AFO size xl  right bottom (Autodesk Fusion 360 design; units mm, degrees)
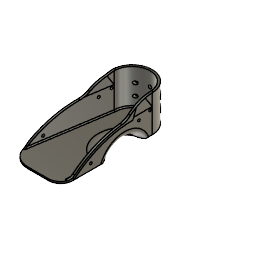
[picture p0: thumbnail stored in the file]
part number: 2025-10-02-12-56-12-317
parameter "d73" = 49
parameter "d131" = 16
sketch "Sketch1" plane through (0, 0, 0) normal (0, 0, 1) x axis (1, 0, 0)
  line L1 (28, -127.4) -> (-48, -127.4)
  line L2 (28, 0) -> (28, -127.4)
  line L3 (25, 0) -> (25, -127.4)
  line L4 (28, 0) -> (25, 0)
  line L5 (-18.603, -127.4) -> (-18.603, -115.6)
  line L6 (10.5, -127.4) -> (10.5, -109.9)
  line L7 (10.5, -127.4) -> (-18.603, -127.4)
  line L8 (36.7314, -101.9) -> (-43.9969, -101.9)
  line L9 (0, 0) -> (-28.984, 0)
  line L10 (-45, -127.4) -> (-25, 0)
  line L11 (-40.9969, -101.9) -> (-44.0794, -101.4161)
  line L12 (-48, -127.4) -> (-28, 0)
  line L13 (-43.6846, -101.9) -> (-43.6828, -102.2021)
  circle C1 centre (0, 0) radius 28
  circle C2 centre (0, 0) radius 25
  circle C3 centre (10.5, -109.9) radius 17.5
  circle C4 centre (-18.1846, -101.9) radius 22.5
  circle C5 centre (10.5, -109.9) radius 14.5
  circle C6 centre (-18.1846, -101.9) radius 25.5
  point P1 (0, 0)
  point P2 (0, 0)
  point P5 (28, 0)
  point P6 (0, 0)
  point P7 (25, 0)
  point P8 (25, -127.4)
  point P13 (-18.603, -127.4)
  point P11 (10.5, -109.9)
  point P14 (10.5, -109.9)
  point P15 (10.5, -127.4)
  point P20 (-25, 0)
  point P21 (-45, -127.4)
  point P22 (-40.9969, -101.9)
  point P10 (-18.1846, -101.9)
  point P25 (-28, 0)
  point P16 (-43.9969, -101.9)
  point P26 (-43.6828, -102.2021)
  point P27 (-43.6846, -101.9)
  point P19 (0, 0)
  coincident P1 P2
  coincident C1 P5
  tangent C1 L2
  perpendicular L1 L2
  coincident P1 P6
  vertical L3
  coincident C2 P7
  perpendicular L2 L4
  coincident L1 P8
  tangent L2 C3
  tangent L1 C3
  concentric C3 C5
  tangent L3 C5
  coincident L1 P13
  perpendicular L1 L5
  coincident P11 P14
  coincident L1 P15
  coincident C3 P15
  perpendicular L1 L6
  perpendicular L5 L8
  horizontal L9
  coincident C2 P20
  coincident L9 P20
  coincident L1 P21
  coincident L10 P22
  coincident L8 P22
  parallel L2 L3
  coincident P10 L8
  concentric C4 C6
  coincident L9 P25
  coincident C1 P25
  parallel L10 L12
  coincident P16 L12
  coincident C6 P26
  coincident L8 P27
  coincident C6 P27
  coincident P1 P19
  tangent L1 C6
  tangent C6 L12
  perpendicular L11 L12
  dimension "d2" diameter C1 = 56 (= "d57 + ( 3 * 2 ) * 1 mm")
  dimension "d4" distance P2 L1 = 127.4 (= "152.4 mm - 25 mm")
  dimension "d57" diameter C2 = 50
  dimension "d74" diameter C3 = 35
  dimension "d252" diameter C4 = 45 (= "d73 - 4 mm")
  dimension "d322" distance P8 P21 = 70
  dimension "d323" diameter C6 = 51 (= "d252 + 6 mm")
extrude "Extrude1" new body sketch "Sketch1" profile of C1 L2 L3 L4 C3 L8 L9 L10 L11 C6 L12 along normal blind 35
extrude "Extrude2" add sketch "Sketch1" profile of C1 L1 L2 C2 L3 C3 C4 C5 L5 L6 L7 L8 L10 L11 C6 L13 along normal blind 3
extrude "Extrude15" new body sketch "Sketch1" profile of C1 C2 L4 L9 along normal blind 178
combine "Combine2"
work_plane "WorkPlane1" RotateAngle -90
fillet "Fillet69" radius 1 1
sketch "Sketch23" plane through (28, 0, 0) normal (1, 0, 0) x axis (0, 1, 0)
  line L1 (-28, 78) -> (0, 35)
  line L2 (-28, 178) -> (-28, 78)
  line L3 (0, 178) -> (-28, 178)
  line L4 (0, 35) -> (0, 178)
  circle C1 centre (-3, 143) radius 1.75
  point P5 (0, 178)
  point P6 (0, 178)
  point P2 (0, 35)
  point P8 (0, 35)
  point P4 (-28, 178)
  point P3 (-28, 78)
  point P7 (-3, 143)
  horizontal L3
  perpendicular L3 L4
  coincident P5 P6
  coincident P2 P8
  parallel L2 L4
  dimension "d253" distance P4 P5 = 28
  dimension "d254" distance P3 P4 = 100
  dimension "d255" diameter C1 = 3.5
  dimension "d256" distance L3 P7 = 35
  dimension "d257" distance L2 P7 = 25
extrude "Extrude18" add sketch "Sketch23" against normal blind 3
mirror "Mirror1" mirrorStitchTolerance 0.1
sketch "Sketch24" plane through (0, 16.0046, 10.4216) normal (0, -0.838, -0.5457) x axis (1, 0, 0)
  line L1 (-25, 80.6427) -> (-25, 29.3299)
  line L2 (-28, 80.6427) -> (-25, 80.6427)
  line L3 (-28, 29.3299) -> (-28, 80.6427)
  line L4 (-25, 62.182) -> (-28, 62.182)
  line L5 (-28, 30.2476) -> (-25, 30.2476)
  line L6 (-28, 30.2476) -> (-28, 62.182)
  line L7 (-25, 62.182) -> (-25, 30.2476)
  line L8 (-25, 29.3299) -> (-28, 29.3299)
  point P6 (-28, 62.182)
  point P7 (-25, 62.182)
  point P8 (-25, 30.2476)
  point P9 (-28, 30.2476)
  coincident L3 P6
  coincident L1 P7
  perpendicular L1 L4
  coincident L1 P8
  coincident L3 P9
  perpendicular L3 L5
sketch "Sketch25" plane through (0, 0, 35) normal (0, 0, 1) x axis (-1, 0, 0)
  line L1 (24.843, -1) -> (27.843, -1)
  line L2 (29.5678, 29.0967) -> (24.843, -1)
  line L3 (32.4956, 28.637) -> (29.5678, 29.0967)
  line L4 (32.4956, 28.637) -> (27.843, -1)
  line L5 (0, 0) -> (28.984, 0)
  line L6 (43.3761, 97.9455) -> (28, 0)
  line L7 (25, 0) -> (40.9969, 101.9)
  line L8 (28, 0) -> (25, 0)
  line L9 (40.9969, 101.9) -> (43.6811, 101.4786)
  arc A1 centre (18.1846, 101.9) radius 25.5 clockwise from (43.6811, 101.4786) to (43.3761, 97.9455)
  point P5 (32.4956, 28.637)
  point P4 (29.5678, 29.0967)
  point P15 (28, 0)
  point P8 (25, 0)
  point P2 (27.843, -1)
  horizontal L1
  coincident P5 L6
  coincident P4 L7
  coincident L4 P15
  coincident L2 P8
  perpendicular L3 L4
  dimension "d280" distance P2 P5 = 30
  dimension "d281" distance L1 L5 = 1
loft "Loft1" sketch "Sketch24" + "Sketch25"
sketch "Sketch26" plane through (0, 0, 35) normal (0, 0, 1) x axis (-1, 0, 0)
  line L1 (-28, 0) -> (-28, 101.9)
  line L2 (-25, 0) -> (-28, 0)
  line L3 (-28, -1) -> (-25, -1)
  line L4 (-28, -1) -> (-28, 29)
  line L5 (-25, 29) -> (-28, 29)
  line L6 (-25, -1) -> (-25, 29)
  line L7 (-28, 101.9) -> (-25, 101.9)
  line L8 (-25, 101.9) -> (-25, 0)
  point P5 (-28, -1)
  point P6 (-28, 29)
  point P7 (-25, 29)
  coincident L1 P5
  perpendicular L1 L3
  coincident L1 P6
  coincident P7 L8
  dimension "d278" distance P5 P6 = 30
  dimension "d279" distance L2 L3 = 1
sketch "Sketch27" plane through (0, 16.0046, 10.4216) normal (0, -0.838, -0.5457) x axis (1, 0, 0)
  line L1 (28, 80.6427) -> (28, 29.3299)
  line L2 (25, 80.6427) -> (28, 80.6427)
  line L3 (25, 29.3299) -> (25, 80.6427)
  line L4 (28, 29.3299) -> (25, 29.3299)
  line L5 (28, 63.1164) -> (25, 63.1164)
  line L6 (28, 32.1164) -> (28, 63.1164)
  line L7 (28, 32.1164) -> (25, 32.1164)
  line L8 (25, 63.1164) -> (25, 32.1164)
  point P6 (25, 63.1164)
  point P7 (28, 63.1164)
  point P8 (28, 32.1164)
  point P9 (25, 32.1164)
  coincident L3 P6
  coincident L1 P7
  perpendicular L1 L5
  coincident L1 P8
  coincident L3 P9
  perpendicular L6 L7
  dimension "d282" distance P7 P8 = 31
loft "Loft2" sketch "Sketch27" + "Sketch26"
work_plane "WorkPlane4" AlongDistance 28 (= "25 mm + 3 mm")
sketch "Sketch9" plane through (0, 28, 0) normal (0, 1, 0) x axis (1, 0, 0)
  circle C1 centre (0, -16) radius 2.25
  circle C2 centre (0, -32) radius 2.25
  circle C3 centre (0, -64) radius 2.25
  circle C4 centre (0, -96) radius 2.25
  circle C5 centre (0, -80) radius 2.25
  circle C6 centre (0, -112) radius 2.25
  circle C7 centre (0, -128) radius 2.25
  circle C8 centre (0, -144) radius 2.25
  point P2 (0, -16)
  point P7 (0, 0)
  point P3 (0, -32)
  point P4 (0, -64)
  point P6 (0, -80)
  point P5 (0, -96)
  point P8 (0, -112)
  point P9 (0, -128)
  point P10 (0, -144)
  dimension "d123" diameter C1 = 4.5
  dimension "d124" diameter C2 = 4.5
  dimension "d126" diameter C3 = 4.5
  dimension "d127" diameter C4 = 4.5
  dimension "d128" diameter C5 = 4.5
  dimension "d129" distance P2 P7 = 16
  dimension "d130" distance P2 P3 = 16
  dimension "d133" distance P4 P6 = 16 (= "d131")
  dimension "d134" distance P5 P6 = 16 (= "d131")
  dimension "d291" diameter C6 = 4.5
  dimension "d292" distance P5 P8 = 16 (= "d131")
  dimension "d293" distance P8 P9 = 16 (= "d130")
  dimension "d294" diameter C7 = 4.5
  dimension "d295" diameter C8 = 4.5
  dimension "d296" distance P9 P10 = 16 (= "d131")
extrude "Extrude20" cut sketch "Sketch9" against normal blind 30
path_pattern "PathPattern3" PathPatternDelta 88.0394
fillet "Fillet51" radius 7 15
fillet "Fillet52" radius 130 130
sphere_primitive "SpherePrimitive3" Diameter 55
move_face "MoveFace3"
boundary_fill "BoundaryFill2"
offset_faces "OffsetFaces2" distance 3
shell "Shell7" innerThickness 2.99
fillet "Fillet74" radius 10 15
hole "Hole6" HoleDepth 106.033 HoleDiameter 3.5 TipAngle 118
hole "Hole7" HoleDepth 106.033 HoleDiameter 3.5 TipAngle 118
work_plane "WorkPlane5" AlongDistance 100
work_plane "WorkPlane6" AlongDistance 51.6037
fillet "Fillet76" radius 30
fillet "Fillet79" radius 25
fillet "Fillet83" radius 22
fillet "Fillet85" radius 30 30
fillet "Fillet86" radius 45
split "Split1"
work_plane "WorkPlane7" AlongDistance -28 (= "-( 56 / 2 ) * 1 mm")
sketch "Sketch35" plane through (-28, 0, 0) normal (1, 0, 0) x axis (0, 1, 0)
  circle C1 centre (-2.7874, 31.4508) radius 6
  dimension "d426" diameter C1 = 12
extrude "Extrude22" add sketch "Sketch35" against normal blind 2
fillet "Fillet87" radius 35
sketch "Sketch33" plane through (27.99, 0, 0) normal (1, 0, 0) x axis (0, 1, 0)
  line L1 (0, 139.3302) -> (0, 52.395)
  line L2 (0, 175.01) -> (0, 146.6698)
  line L3 (-11.056, 175.01) -> (0, 175.01)
  line L4 (-25.01, 78.8877) -> (-25.01, 161.056)
  line L5 (-15.1078, 63.6808) -> (-25.01, 78.8877)
  line L6 (-16.1988, 60.7566) -> (-15.1078, 63.6808)
  line L7 (2, 178) -> (28, 178)
  arc A1 centre (7.4005, 86.6037) radius 35 clockwise from (0, 52.395) to (-16.1988, 60.7566)
  arc A2 centre (-3, 143) radius 4.74 clockwise from (0, 139.3302) to (0, 146.6698)
  arc A3 centre (2, 148) radius 30 clockwise from (-25.01, 161.056) to (-11.056, 175.01)
  circle C1 centre (-3, 128) radius 1.5
  circle C2 centre (-3, 98) radius 1.7185
  circle C3 centre (-3, 32) radius 1.75
  point P16 (-3, 128)
  point P17 (-3, 98)
  point P18 (-3, 32)
  vertical P16 P17
  vertical P17 P18
  dimension "d413" diameter C1 = 3
  dimension "d414" distance P16 P17 = 30
  dimension "d415" diameter C3 = 3.5
  dimension "d416" distance P17 P18 = 66
  dimension "d417" distance P16 L7 = 50
  dimension "d418" distance L1 P16 = 3
extrude "Extrude21" cut sketch "Sketch33" profile of C1 C2 C3 against normal blind 133.937
fillet "Fillet88" radius 36
sketch "Sketch37" plane through (-28, 0, 0) normal (1, 0, 0) x axis (0, 1, 0)
fillet "Fillet98" radius 48
fillet "Fillet99" radius 48
sketch "Sketch38" plane through (-28, 0, 0) normal (1, 0, 0) x axis (0, 1, 0)
  line L1 (-5.5406, 132.8689) -> (0, 132.8689)
  line L2 (-5.5406, 93.572) -> (-5.5406, 132.8689)
  line L3 (0, 93.572) -> (-5.5406, 93.572)
  line L4 (0, 132.8689) -> (0, 93.572)
  horizontal L1
  vertical L2
  horizontal L3
  vertical L4
extrude "Extrude24" add sketch "Sketch38" along normal blind 1 and against normal blind 2
fillet "Fillet91" radius 2 2 2 2
fillet "Fillet92" radius 0.5
extrude "Extrude25" cut sketch "Sketch33" profile of C1 C2 against normal blind 188.494
work_plane "WorkPlane8" AlongDistance 178
sketch "Sketch39" plane through (0, 0, 178) normal (0, 0, 1) x axis (1, 0, 0)
  line L1 (-25, 0) -> (25, 0)
  line L2 (30, 0) -> (25, 0)
  line L3 (-32, 0) -> (-25, 0)
  arc A1 centre (0, 10.2) radius 29.8 clockwise from (-28, 0) to (28, 0)
  point P7 (-28, 0)
  horizontal L1
  parallel L1 L2
  parallel L1 L3
  coincident L3 P7
revolve "Revolve2" sketch "Sketch39" AlongAngle -30
fillet "Fillet95" radius 20 20
fillet "Fillet97" radius 1.5
fillet "Fillet100" radius 0.2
